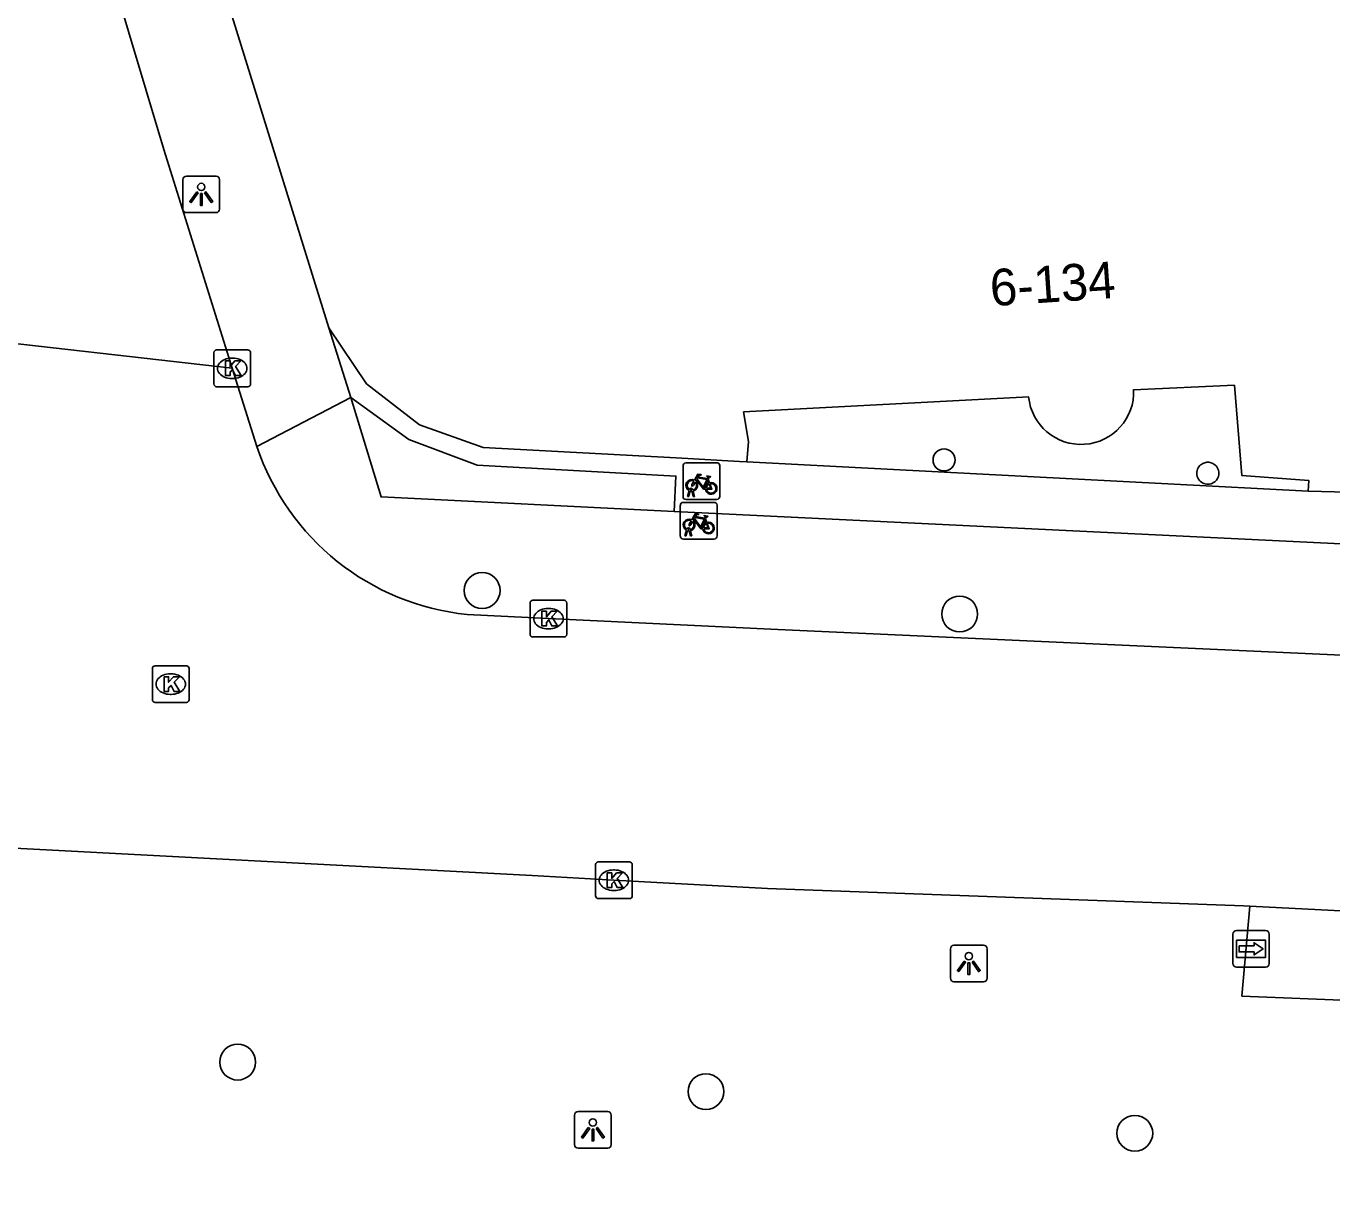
# Model space of a CAD drawing. Extents: x 161253 to 161848, y 384872 to 385383.
# Drawn here: x 161454.75 to 161490.34, y 384882.04 to 384913.66 of the extents above; entities that cross this region are included whole.
import ezdxf

# ---------------------------------------------------------------- set-up
doc = ezdxf.new("R2010")
doc.units = 0
for name, color, linetype in [('IMGEO_Boom', 7, 'Continuous'), ('IMGEO_Fietsenrek', 7, 'Continuous'), ('IMGEO_Haag', 7, 'Continuous'), ('IMGEO_Kolk', 7, 'Continuous'), ('IMGEO_Lichtpunt', 7, 'Continuous'), ('IMGEO_Pand', 7, 'Continuous'), ('IMGEO_Pand_nummerreeks', 7, 'Continuous'), ('IMGEO_Pand_overbouw', 7, 'Continuous'), ('IMGEO_Rijbaan_lokaal_open', 7, 'Continuous'), ('IMGEO_Voetpad_open', 7, 'Continuous'), ('IMGEO_Wegwijzer', 7, 'Continuous')]:
    doc.layers.add(name, color=color, linetype=linetype)

msp = doc.modelspace()

# ---------------------------------------------------------------- linework, layer by layer
at = {"layer": 'IMGEO_Boom'}
for centre in [(161467.18, 384898.275), (161480.198, 384897.634), (161460.516, 384885.417), (161473.282, 384884.612), (161484.971, 384883.476)]:
    msp.add_circle(centre, 0.489, dxfattribs=at)
at = {"layer": 'IMGEO_Fietsenrek'}
for p, q in [((161472.731, 384901.757), (161473.572, 384901.757)), ((161473.572, 384901.757), (161472.731, 384901.757)), ((161472.656, 384900.832), (161472.656, 384901.673)), ((161472.656, 384901.673), (161472.656, 384900.832)), ((161473.656, 384901.682), (161473.656, 384900.841)), ((161473.656, 384900.841), (161473.656, 384901.682)), ((161473.343, 384901.306), (161473.379, 384901.211)), ((161473.581, 384900.757), (161472.74, 384900.757)), ((161472.74, 384900.757), (161473.581, 384900.757)), ((161472.783, 384900.841), (161472.822, 384901.001)), ((161472.817, 384900.841), (161472.783, 384900.841)), ((161472.852, 384900.989), (161472.817, 384900.841)), ((161472.894, 384901.013), (161472.893, 384901.017)), ((161472.935, 384900.841), (161472.901, 384900.983)), ((161472.925, 384901.024), (161472.926, 384901.017)), ((161472.933, 384900.987), (161472.968, 384900.841)), ((161472.968, 384900.841), (161472.935, 384900.841)), ((161472.583, 384899.753), (161472.583, 384900.594)), ((161472.583, 384900.594), (161472.583, 384899.753)), ((161472.658, 384900.678), (161473.499, 384900.678)), ((161473.499, 384900.678), (161472.658, 384900.678)), ((161473.583, 384900.603), (161473.583, 384899.762)), ((161473.583, 384899.762), (161473.583, 384900.603)), ((161473.27, 384900.227), (161473.306, 384900.132)), ((161473.508, 384899.678), (161472.667, 384899.678)), ((161472.667, 384899.678), (161473.508, 384899.678)), ((161472.71, 384899.762), (161472.749, 384899.922)), ((161472.744, 384899.762), (161472.71, 384899.762)), ((161472.779, 384899.91), (161472.744, 384899.762)), ((161472.821, 384899.934), (161472.82, 384899.938)), ((161472.862, 384899.762), (161472.828, 384899.904)), ((161472.852, 384899.945), (161472.853, 384899.938)), ((161472.86, 384899.908), (161472.895, 384899.762)), ((161472.895, 384899.762), (161472.862, 384899.762))]:
    msp.add_line(p, q, dxfattribs=at)
for points in [[(161472.969, 384901.283), (161473.064, 384901.447), (161473.15, 384901.433), (161473.152, 384901.424), (161473.096, 384901.413), (161473.069, 384901.368), (161473.325, 384901.327)], [(161473.325, 384901.327), (161473.35, 384901.376), (161473.344, 384901.38), (161473.321, 384901.384), (161473.309, 384901.391), (161473.308, 384901.394), (161473.31, 384901.399), (161473.405, 384901.384), (161473.407, 384901.374), (161473.397, 384901.361), (161473.385, 384901.355), (161473.371, 384901.361), (161473.343, 384901.306)], [(161472.99, 384901.231), (161472.938, 384901.141), (161472.898, 384901.116), (161472.899, 384901.163), (161472.954, 384901.257)], [(161473.265, 384901.039), (161473.215, 384901.039), (161473.024, 384901.29), (161473.005, 384901.258)], [(161473.312, 384901.302), (161473.055, 384901.343), (161473.038, 384901.314), (161473.205, 384901.094), (161473.312, 384901.302)], [(161473.36, 384901.204), (161473.33, 384901.281), (161473.221, 384901.063), (161473.264, 384901.063)], [(161473.294, 384901.063), (161473.414, 384901.062), (161473.37, 384901.176)], [(161473.39, 384901.183), (161473.445, 384901.038), (161473.295, 384901.038)], [(161472.896, 384900.204), (161472.991, 384900.368), (161473.077, 384900.354), (161473.079, 384900.345), (161473.023, 384900.334), (161472.996, 384900.289), (161473.252, 384900.248)], [(161472.917, 384900.152), (161472.865, 384900.062), (161472.825, 384900.037), (161472.826, 384900.084), (161472.881, 384900.178)], [(161473.192, 384899.96), (161473.142, 384899.96), (161472.951, 384900.211), (161472.932, 384900.179)], [(161473.239, 384900.223), (161472.982, 384900.264), (161472.965, 384900.235), (161473.132, 384900.015), (161473.239, 384900.223)], [(161473.287, 384900.125), (161473.257, 384900.202), (161473.148, 384899.984), (161473.191, 384899.984)], [(161473.221, 384899.984), (161473.341, 384899.983), (161473.297, 384900.097)], [(161473.317, 384900.104), (161473.372, 384899.959), (161473.222, 384899.959)], [(161473.252, 384900.248), (161473.277, 384900.297), (161473.271, 384900.301), (161473.248, 384900.305), (161473.236, 384900.312), (161473.235, 384900.315), (161473.237, 384900.32), (161473.332, 384900.305), (161473.334, 384900.295), (161473.324, 384900.282), (161473.312, 384900.276), (161473.298, 384900.282), (161473.27, 384900.227)]]:
    msp.add_lwpolyline(points, dxfattribs=at)
for centre, radius, start, end in [((161472.734, 384901.679), 0.0779, 92.4484, 184.2845), ((161472.734, 384901.679), 0.0779, 92.4484, 184.2845), ((161473.578, 384901.679), 0.0779, 2.4484, 94.2845), ((161473.578, 384901.679), 0.0779, 2.4484, 94.2845), ((161472.896, 384901.142), 0.159, 62.6766, 242.1369), ((161472.896, 384901.142), 0.129, 63.3192, 238.903), ((161472.876, 384901.013), 0.0499, 12.8025, 158.6934), ((161472.896, 384901.142), 0.129, 283.6043, 43.4302), ((161472.896, 384901.142), 0.159, 283.5766, 46.6042), ((161473.423, 384901.058), 0.159, 113.3408, 178.3217), ((161473.423, 384901.058), 0.159, 187.0065, 105.7708), ((161473.423, 384901.058), 0.129, 113.923, 177.9556), ((161473.423, 384901.058), 0.129, 188.6715, 104.5883), ((161472.734, 384900.835), 0.0779, 182.4484, 274.2845), ((161472.734, 384900.835), 0.0779, 182.4484, 274.2845), ((161472.896, 384901.142), 0.159, 253.9967, 271.7867), ((161472.876, 384901.013), 0.0174, 12.8025, 163.4502), ((161472.896, 384901.142), 0.129, 253.415, 269.0204), ((161473.578, 384900.835), 0.0779, 272.4484, 4.2845), ((161473.578, 384900.835), 0.0779, 272.4484, 4.2845), ((161472.661, 384900.6), 0.0779, 92.4484, 184.2845), ((161472.661, 384900.6), 0.0779, 92.4484, 184.2845), ((161473.505, 384900.6), 0.0779, 2.4484, 94.2845), ((161473.505, 384900.6), 0.0779, 2.4484, 94.2845), ((161472.823, 384900.063), 0.159, 62.6766, 242.1369), ((161472.823, 384900.063), 0.129, 63.3192, 238.903), ((161472.803, 384899.934), 0.0499, 12.8025, 158.6934), ((161472.823, 384900.063), 0.129, 283.6043, 43.4302), ((161472.823, 384900.063), 0.159, 283.5766, 46.6042), ((161473.35, 384899.979), 0.159, 113.3408, 178.3217), ((161473.35, 384899.979), 0.159, 187.0065, 105.7708), ((161473.35, 384899.979), 0.129, 113.923, 177.9556), ((161473.35, 384899.979), 0.129, 188.6715, 104.5883), ((161472.661, 384899.756), 0.0779, 182.4484, 274.2845), ((161472.661, 384899.756), 0.0779, 182.4484, 274.2845), ((161472.823, 384900.063), 0.159, 253.9967, 271.7867), ((161472.803, 384899.934), 0.0174, 12.8025, 163.4502), ((161472.823, 384900.063), 0.129, 253.415, 269.0204), ((161473.505, 384899.756), 0.0779, 272.4484, 4.2845), ((161473.505, 384899.756), 0.0779, 272.4484, 4.2845)]:
    msp.add_arc(centre, radius, start, end, dxfattribs=at)
at = {"layer": 'IMGEO_Haag'}
for points in [[(161463.597, 384903.538), (161465.178, 384902.396), (161467.049, 384901.693), (161472.464, 384901.396), (161472.417, 384900.431)], [(161594.709, 384882.686), (161587.754, 384882.945), (161578.585, 384883.414), (161564.755, 384883.961), (161553.631, 384884.443), (161549.641, 384884.61), (161543.014, 384884.888), (161528.41, 384885.51), (161516.282, 384885.98), (161504.167, 384886.488), (161500, 384886.678), (161491.061, 384887.085), (161487.893, 384887.217), (161488.111, 384889.666)]]:
    msp.add_lwpolyline(points, dxfattribs=at)
at = {"layer": 'IMGEO_Kolk'}
for p, q in [((161459.867, 384903.906), (161459.867, 384904.758)), ((161459.942, 384904.832), (161460.794, 384904.832)), ((161460.355, 384904.612), (161460.38, 384904.612)), ((161460.868, 384904.758), (161460.868, 384903.906)), ((161460.378, 384904.052), (161460.353, 384904.052)), ((161460.794, 384903.832), (161459.942, 384903.832)), ((161468.487, 384897.081), (161468.487, 384897.933)), ((161468.562, 384898.007), (161469.414, 384898.007)), ((161469.488, 384897.933), (161469.488, 384897.081)), ((161468.975, 384897.787), (161469, 384897.787)), ((161468.998, 384897.227), (161468.973, 384897.227)), ((161469.414, 384897.007), (161468.562, 384897.007)), ((161458.191, 384895.296), (161458.191, 384896.148)), ((161458.266, 384896.222), (161459.118, 384896.222)), ((161459.192, 384896.148), (161459.192, 384895.296)), ((161458.679, 384896.002), (161458.704, 384896.002)), ((161458.702, 384895.442), (161458.677, 384895.442)), ((161459.118, 384895.222), (161458.266, 384895.222)), ((161470.271, 384889.95), (161470.271, 384890.802)), ((161470.346, 384890.876), (161471.198, 384890.876)), ((161471.272, 384890.802), (161471.272, 384889.95)), ((161470.759, 384890.656), (161470.784, 384890.656)), ((161470.782, 384890.096), (161470.757, 384890.096)), ((161471.198, 384889.876), (161470.346, 384889.876))]:
    msp.add_line(p, q, dxfattribs=at)
for points in [[(161459.867, 384903.906), (161459.867, 384904.758)], [(161459.942, 384904.832), (161460.794, 384904.832)], [(161460.868, 384904.758), (161460.868, 384903.906)], [(161460.188, 384904.532), (161460.311, 384904.532), (161460.311, 384904.381), (161460.441, 384904.532), (161460.605, 384904.532), (161460.459, 384904.381), (161460.612, 384904.132), (161460.46, 384904.132), (161460.375, 384904.296), (161460.311, 384904.229), (161460.311, 384904.132), (161460.188, 384904.132), (161460.188, 384904.532)], [(161460.794, 384903.832), (161459.942, 384903.832)], [(161468.487, 384897.081), (161468.487, 384897.933)], [(161468.562, 384898.007), (161469.414, 384898.007)], [(161469.488, 384897.933), (161469.488, 384897.081)], [(161468.808, 384897.707), (161468.931, 384897.707), (161468.931, 384897.556), (161469.061, 384897.707), (161469.225, 384897.707), (161469.079, 384897.556), (161469.232, 384897.307), (161469.08, 384897.307), (161468.995, 384897.471), (161468.931, 384897.404), (161468.931, 384897.307), (161468.808, 384897.307), (161468.808, 384897.707)], [(161469.414, 384897.007), (161468.562, 384897.007)], [(161458.191, 384895.296), (161458.191, 384896.148)], [(161458.266, 384896.222), (161459.118, 384896.222)], [(161459.192, 384896.148), (161459.192, 384895.296)], [(161458.512, 384895.922), (161458.635, 384895.922), (161458.635, 384895.771), (161458.765, 384895.922), (161458.929, 384895.922), (161458.783, 384895.771), (161458.936, 384895.522), (161458.784, 384895.522), (161458.699, 384895.686), (161458.635, 384895.619), (161458.635, 384895.522), (161458.512, 384895.522), (161458.512, 384895.922)], [(161459.118, 384895.222), (161458.266, 384895.222)], [(161470.271, 384889.95), (161470.271, 384890.802)], [(161470.346, 384890.876), (161471.198, 384890.876)], [(161471.272, 384890.802), (161471.272, 384889.95)], [(161470.592, 384890.576), (161470.715, 384890.576), (161470.715, 384890.425), (161470.845, 384890.576), (161471.009, 384890.576), (161470.863, 384890.425), (161471.016, 384890.176), (161470.864, 384890.176), (161470.779, 384890.34), (161470.715, 384890.273), (161470.715, 384890.176), (161470.592, 384890.176), (161470.592, 384890.576)], [(161471.198, 384889.876), (161470.346, 384889.876)]]:
    msp.add_lwpolyline(points, dxfattribs=at)
for centre, start, end in [((161459.944, 384904.756), 91.552, 178.448), ((161459.944, 384904.756), 91.552, 178.448), ((161460.792, 384904.756), 1.552, 88.448), ((161460.792, 384904.756), 1.552, 88.448), ((161459.944, 384903.908), 181.552, 268.448), ((161459.944, 384903.908), 181.552, 268.448), ((161460.792, 384903.908), 271.552, 358.448), ((161460.792, 384903.908), 271.552, 358.448), ((161468.564, 384897.931), 91.552, 178.448), ((161468.564, 384897.931), 91.552, 178.448), ((161469.412, 384897.931), 1.552, 88.448), ((161469.412, 384897.931), 1.552, 88.448), ((161468.564, 384897.083), 181.552, 268.448), ((161468.564, 384897.083), 181.552, 268.448), ((161469.412, 384897.083), 271.552, 358.448), ((161469.412, 384897.083), 271.552, 358.448), ((161458.268, 384896.146), 91.552, 178.448), ((161458.268, 384896.146), 91.552, 178.448), ((161459.116, 384896.146), 1.552, 88.448), ((161459.116, 384896.146), 1.552, 88.448), ((161458.268, 384895.298), 181.552, 268.448), ((161458.268, 384895.298), 181.552, 268.448), ((161459.116, 384895.298), 271.552, 358.448), ((161459.116, 384895.298), 271.552, 358.448), ((161470.348, 384890.8), 91.552, 178.448), ((161470.348, 384890.8), 91.552, 178.448), ((161471.196, 384890.8), 1.552, 88.448), ((161471.196, 384890.8), 1.552, 88.448), ((161470.348, 384889.952), 181.552, 268.448), ((161470.348, 384889.952), 181.552, 268.448), ((161471.196, 384889.952), 271.552, 358.448), ((161471.196, 384889.952), 271.552, 358.448)]:
    msp.add_arc(centre, 0.0765, start, end, dxfattribs=at)
for centre, major_axis, ratio, start_param, end_param in [((161460.354, 384904.332), (-0.387, 0.002), 0.722429, 4.712389, 7.853982), ((161460.379, 384904.332), (-0.39, 0.002), 0.717154, 1.570796, 4.712389), ((161468.974, 384897.507), (-0.387, 0.002), 0.722429, 4.712389, 7.853982), ((161468.999, 384897.507), (-0.39, 0.002), 0.717154, 1.570796, 4.712389), ((161458.678, 384895.722), (-0.387, 0.002), 0.722429, 4.712389, 7.853982), ((161458.703, 384895.722), (-0.39, 0.002), 0.717154, 1.570796, 4.712389), ((161470.758, 384890.376), (-0.387, 0.002), 0.722429, 4.712389, 7.853982), ((161470.783, 384890.376), (-0.39, 0.002), 0.717154, 1.570796, 4.712389)]:
    msp.add_ellipse(centre, major_axis=major_axis, ratio=ratio, start_param=start_param, end_param=end_param, dxfattribs=at)
at = {"layer": 'IMGEO_Lichtpunt'}
for p, q in [((161459.025, 384909.479), (161459.025, 384908.672)), ((161459.025, 384909.479), (161459.025, 384908.672)), ((161459.927, 384909.574), (161459.119, 384909.574)), ((161459.927, 384909.574), (161459.119, 384909.574)), ((161460.021, 384908.672), (161460.021, 384909.479)), ((161460.021, 384908.672), (161460.021, 384909.479)), ((161459.119, 384908.578), (161459.927, 384908.578)), ((161459.119, 384908.578), (161459.927, 384908.578)), ((161480.85, 384888.604), (161480.042, 384888.604)), ((161480.85, 384888.604), (161480.042, 384888.604)), ((161479.948, 384888.509), (161479.948, 384887.702)), ((161479.948, 384888.509), (161479.948, 384887.702)), ((161480.944, 384887.702), (161480.944, 384888.509)), ((161480.944, 384887.702), (161480.944, 384888.509)), ((161480.042, 384887.608), (161480.85, 384887.608)), ((161480.042, 384887.608), (161480.85, 384887.608)), ((161469.701, 384883.973), (161469.701, 384883.166)), ((161469.701, 384883.973), (161469.701, 384883.166)), ((161470.603, 384884.068), (161469.795, 384884.068)), ((161470.603, 384884.068), (161469.795, 384884.068)), ((161470.697, 384883.166), (161470.697, 384883.973)), ((161470.697, 384883.166), (161470.697, 384883.973)), ((161469.795, 384883.072), (161470.603, 384883.072)), ((161469.795, 384883.072), (161470.603, 384883.072))]:
    msp.add_line(p, q, dxfattribs=at)
for points in [[(161459.399, 384909.143), (161459.438, 384909.115), (161459.25, 384908.853), (161459.212, 384908.88), (161459.399, 384909.143)], [(161459.501, 384909.095), (161459.548, 384909.095), (161459.548, 384908.773), (161459.501, 384908.773), (161459.501, 384909.095)], [(161459.611, 384909.115), (161459.649, 384909.142), (161459.836, 384908.88), (161459.797, 384908.852), (161459.611, 384909.115)], [(161480.322, 384888.173), (161480.361, 384888.145), (161480.173, 384887.883), (161480.135, 384887.91), (161480.322, 384888.173)], [(161480.424, 384888.125), (161480.471, 384888.125), (161480.471, 384887.803), (161480.424, 384887.803), (161480.424, 384888.125)], [(161480.534, 384888.145), (161480.572, 384888.172), (161480.759, 384887.91), (161480.72, 384887.882), (161480.534, 384888.145)], [(161470.075, 384883.637), (161470.114, 384883.609), (161469.926, 384883.347), (161469.888, 384883.374), (161470.075, 384883.637)], [(161470.287, 384883.609), (161470.325, 384883.636), (161470.512, 384883.374), (161470.473, 384883.346), (161470.287, 384883.609)], [(161470.177, 384883.589), (161470.224, 384883.589), (161470.224, 384883.267), (161470.177, 384883.267), (161470.177, 384883.589)]]:
    msp.add_lwpolyline(points, dxfattribs=at)
for centre in [(161459.524, 384909.277), (161480.447, 384888.307), (161470.2, 384883.771)]:
    msp.add_circle(centre, 0.0994, dxfattribs=at)
for centre, start, end in [((161459.119, 384909.479), 90, 180), ((161459.119, 384909.479), 90, 180), ((161459.927, 384909.479), 0, 90), ((161459.927, 384909.479), 0, 90), ((161459.119, 384908.672), 180, 270), ((161459.119, 384908.672), 180, 270), ((161459.927, 384908.672), 270, 0), ((161459.927, 384908.672), 270, 360), ((161480.042, 384888.509), 90, 180), ((161480.042, 384888.509), 90, 180), ((161480.85, 384888.509), 0, 90), ((161480.85, 384888.509), 0, 90), ((161480.042, 384887.702), 180, 270), ((161480.042, 384887.702), 180, 270), ((161480.85, 384887.702), 270, 0), ((161480.85, 384887.702), 270, 360), ((161469.795, 384883.973), 90, 180), ((161469.795, 384883.973), 90, 180), ((161470.603, 384883.973), 0, 90), ((161470.603, 384883.973), 0, 90), ((161469.795, 384883.166), 180, 270), ((161469.795, 384883.166), 180, 270), ((161470.603, 384883.166), 270, 0), ((161470.603, 384883.166), 270, 360)]:
    msp.add_arc(centre, 0.0946, start, end, dxfattribs=at)
at = {"layer": 'IMGEO_Pand'}
for points in [[(161459.171, 384917.798), (161462.997, 384905.435)], [(161462.997, 384905.435), (161464.028, 384903.912), (161465.471, 384902.789), (161467.205, 384902.169), (161472.472, 384901.888), (161474.197, 384901.793), (161474.4, 384901.782), (161474.445, 384902.333), (161474.306, 384903.145), (161482.079, 384903.557)], [(161484.941, 384903.75), (161487.689, 384903.87), (161487.889, 384901.412), (161489.713, 384901.276), (161489.698, 384900.984), (161491.494, 384900.934), (161492.153, 384900.901), (161500, 384900.507), (161531.936, 384898.905)]]:
    msp.add_lwpolyline(points, dxfattribs=at)
for centre, radius, start, end in [((161483.507, 384903.692), 1.435, 185.3791, 2.3367), ((161479.771, 384901.835), 0.3, 90, 270), ((161479.771, 384901.835), 0.3, 270, 90), ((161486.962, 384901.471), 0.3, 309.5127, 128.7029), ((161486.962, 384901.471), 0.3, 128.5585, 309.6571)]:
    msp.add_arc(centre, radius, start, end, dxfattribs=at)
at = {"layer": 'IMGEO_Pand_overbouw'}
msp.add_lwpolyline([(161482.079, 384903.557), (161474.306, 384903.145), (161474.445, 384902.333), (161474.4, 384901.782), (161489.698, 384900.984), (161489.713, 384901.276), (161487.889, 384901.412), (161487.689, 384903.87), (161484.941, 384903.75)], dxfattribs=at)
msp.add_arc((161483.507, 384903.692), 1.435, 185.3791, 2.3367, dxfattribs=at)
at = {"layer": 'IMGEO_Rijbaan_lokaal_open'}
for points in [[(161460.368, 384904.332), (161458.507, 384910.295), (161456.119, 384918.262), (161453.927, 384925.402), (161451.635, 384932.866), (161448.004, 384944.929)], [(161460.368, 384904.332), (161452.677, 384905.212)], [(161461.041, 384902.205), (161460.368, 384904.332)], [(161466.772, 384897.621), (161468.988, 384897.507), (161475.245, 384897.212), (161500, 384896.083), (161532.296, 384894.342)], [(161488.111, 384889.666), (161487.937, 384889.675), (161474.955, 384890.148), (161470.772, 384890.376), (161468.545, 384890.508), (161452.703, 384891.345), (161438.246, 384892.076), (161437.485, 384892.094)], [(161636.436, 384882.042), (161636.065, 384882.074), (161627.749, 384882.49), (161590.763, 384884.545), (161577.48, 384885.18), (161562.977, 384885.929), (161549.736, 384886.572), (161541.795, 384886.958), (161531.242, 384887.453), (161519.101, 384888.088), (161509.031, 384888.583), (161500, 384889.054), (161497.843, 384889.167), (161488.111, 384889.666)]]:
    msp.add_lwpolyline(points, dxfattribs=at)
msp.add_arc((161467.459, 384904.355), 6.769, 198.5195, 264.1707, dxfattribs=at)
at = {"layer": 'IMGEO_Voetpad_open'}
for points in [[(161462.997, 384905.435), (161463.597, 384903.538)], [(161463.597, 384903.538), (161461.041, 384902.205)], [(161472.417, 384900.431), (161464.426, 384900.827), (161463.597, 384903.538)], [(161531.851, 384897.478), (161511.33, 384898.504), (161500, 384899.077), (161492.094, 384899.477), (161472.417, 384900.431)]]:
    msp.add_lwpolyline(points, dxfattribs=at)
at = {"layer": 'IMGEO_Wegwijzer'}
for p, q in [((161487.747, 384889.005), (161488.537, 384889.005)), ((161488.537, 384889.005), (161487.747, 384889.005)), ((161487.647, 384888.105), (161487.647, 384888.905)), ((161487.647, 384888.905), (161487.647, 384888.105)), ((161488.637, 384888.905), (161488.637, 384888.105)), ((161488.637, 384888.105), (161488.637, 384888.905)), ((161488.537, 384888.005), (161487.747, 384888.005)), ((161487.747, 384888.005), (161488.537, 384888.005))]:
    msp.add_line(p, q, dxfattribs=at)
for points in [[(161487.748, 384888.737), (161488.536, 384888.737), (161488.536, 384888.273), (161487.748, 384888.273), (161487.748, 384888.737)], [(161487.813, 384888.589), (161487.813, 384888.505), (161487.813, 384888.421), (161488.224, 384888.421), (161488.224, 384888.338), (161488.471, 384888.505), (161488.224, 384888.672), (161488.224, 384888.589), (161487.813, 384888.589)]]:
    msp.add_lwpolyline(points, dxfattribs=at)
for centre, start, end in [((161487.747, 384888.905), 90, 180), ((161487.747, 384888.905), 90, 180), ((161488.537, 384888.905), 0, 90), ((161488.537, 384888.905), 360, 90), ((161487.747, 384888.105), 180, 270), ((161487.747, 384888.105), 180, 270), ((161488.537, 384888.105), 270, 0), ((161488.537, 384888.105), 270, 0)]:
    msp.add_arc(centre, 0.1, start, end, dxfattribs=at)

# ---------------------------------------------------------------- texts
at = {"layer": 'IMGEO_Pand_nummerreeks'}
msp.add_text('6-134', height=1, rotation=3.8443, dxfattribs=at).set_placement((161481.056, 384906.024))

doc.saveas('drawing.dxf')
